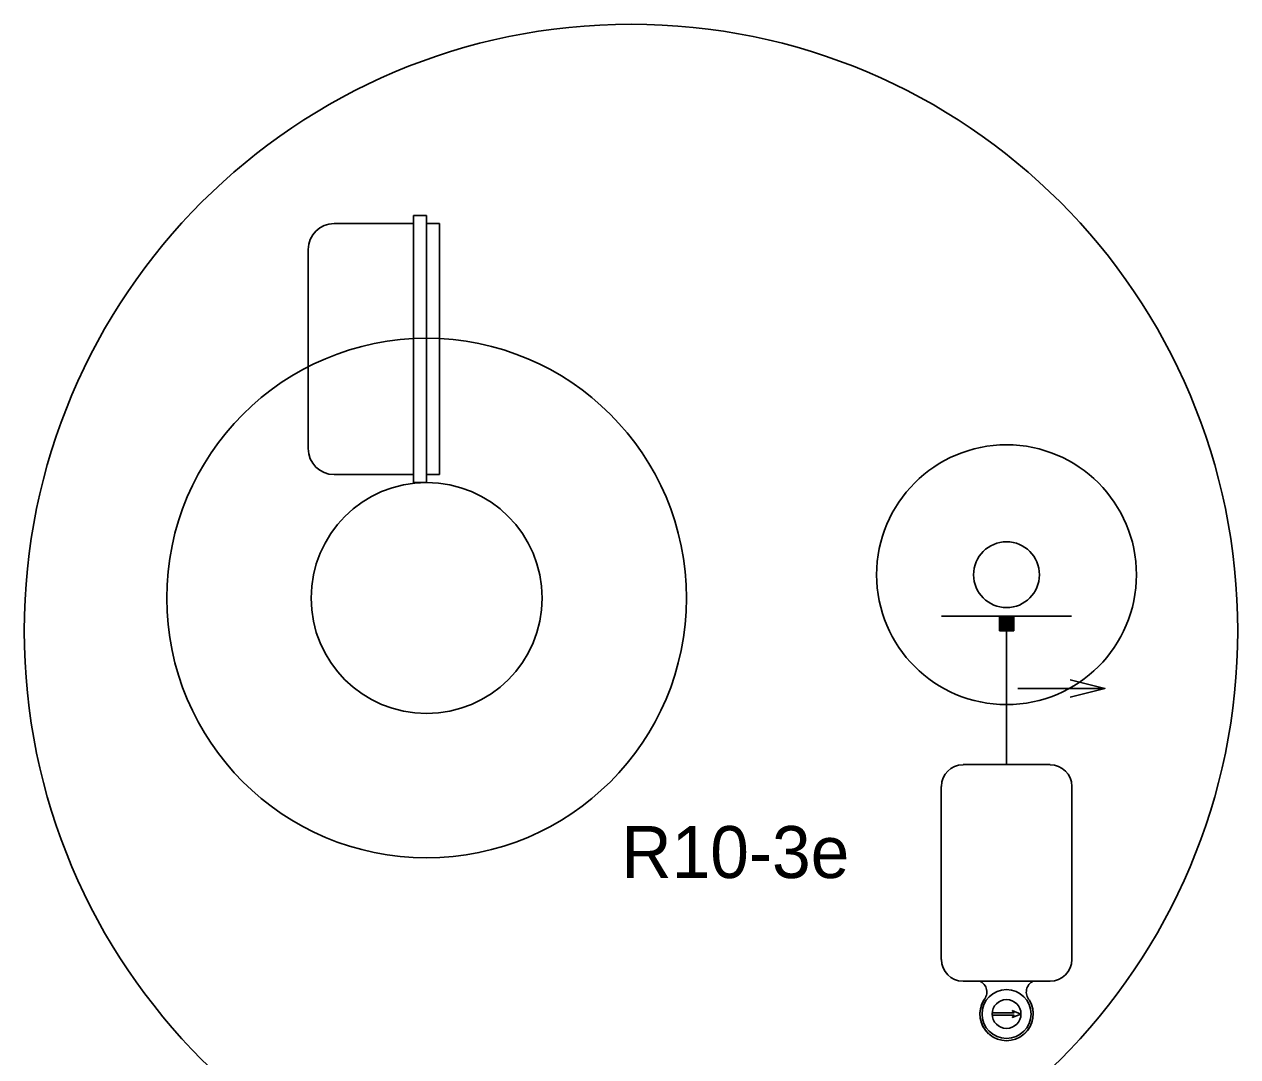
# Model space of a CAD drawing. Extents: x 418532 to 420296, y -565948 to -565286.
# Drawn here: x 419463.9 to 419569, y -565709.5 to -565620 of the extents above; entities that cross this region are included whole.
import ezdxf

# ---------------------------------------------------------------- set-up
doc = ezdxf.new("R2010")
doc.units = 0
doc.layers.add('T_Drafting', color=7, linetype='Continuous')

msp = doc.modelspace()

# ---------------------------------------------------------------- linework, layer by layer
at = {"layer": 'T_Drafting'}
for p, q in [((419497.65, -565659.72), (419497.65, -565636.59)), ((419498.78, -565636.59), (419497.65, -565636.59)), ((419498.78, -565659.72), (419498.78, -565636.59)), ((419497.65, -565637.28), (419490.78, -565637.28)), ((419499.9, -565637.28), (419498.78, -565637.28)), ((419499.9, -565659.03), (419499.9, -565637.28)), ((419488.53, -565656.78), (419488.53, -565639.53)), ((419497.65, -565659.03), (419490.78, -565659.03)), ((419498.78, -565659.72), (419497.65, -565659.72)), ((419499.9, -565659.03), (419498.78, -565659.03)), ((419554.63, -565671.3), (419543.38, -565671.3)), ((419548.38, -565672.55), (419548.38, -565671.3)), ((419548.38, -565672.54), (419549.62, -565671.3)), ((419548.38, -565672.52), (419549.6, -565671.3)), ((419548.38, -565672.5), (419549.58, -565671.3)), ((419548.38, -565672.47), (419549.56, -565671.3)), ((419548.38, -565672.45), (419549.54, -565671.3)), ((419548.38, -565672.43), (419549.51, -565671.3)), ((419548.38, -565672.41), (419549.49, -565671.3)), ((419548.38, -565672.39), (419549.47, -565671.3)), ((419548.38, -565672.37), (419549.45, -565671.3)), ((419548.38, -565672.35), (419549.43, -565671.3)), ((419548.38, -565672.33), (419549.41, -565671.3)), ((419548.38, -565672.3), (419549.39, -565671.3)), ((419548.38, -565672.28), (419549.37, -565671.3)), ((419548.38, -565672.26), (419549.34, -565671.3)), ((419548.38, -565672.24), (419549.32, -565671.3)), ((419548.38, -565672.22), (419549.3, -565671.3)), ((419548.38, -565672.2), (419549.28, -565671.3)), ((419548.38, -565672.18), (419549.26, -565671.3)), ((419548.38, -565672.16), (419549.24, -565671.3)), ((419548.38, -565672.14), (419549.22, -565671.3)), ((419548.38, -565672.11), (419549.2, -565671.3)), ((419548.38, -565672.09), (419549.17, -565671.3)), ((419548.38, -565672.07), (419549.15, -565671.3)), ((419548.38, -565672.05), (419549.13, -565671.3)), ((419548.38, -565672.03), (419549.11, -565671.3)), ((419548.38, -565672.01), (419549.09, -565671.3)), ((419548.38, -565671.99), (419549.07, -565671.3)), ((419548.38, -565671.97), (419549.05, -565671.3)), ((419548.38, -565671.94), (419549.03, -565671.3)), ((419548.38, -565671.92), (419549.01, -565671.3)), ((419548.38, -565671.9), (419548.98, -565671.3)), ((419548.38, -565671.88), (419548.96, -565671.3)), ((419548.38, -565671.86), (419548.94, -565671.3)), ((419548.38, -565671.84), (419548.92, -565671.3)), ((419548.38, -565671.82), (419548.9, -565671.3)), ((419548.38, -565671.8), (419548.88, -565671.3)), ((419548.38, -565671.77), (419548.86, -565671.3)), ((419548.38, -565671.75), (419548.84, -565671.3)), ((419548.38, -565671.73), (419548.81, -565671.3)), ((419548.38, -565671.71), (419548.79, -565671.3)), ((419548.38, -565671.69), (419548.77, -565671.3)), ((419548.38, -565671.67), (419548.75, -565671.3)), ((419548.38, -565671.65), (419548.73, -565671.3)), ((419548.38, -565671.63), (419548.71, -565671.3)), ((419548.38, -565671.6), (419548.69, -565671.3)), ((419548.38, -565671.58), (419548.67, -565671.3)), ((419548.38, -565671.56), (419548.64, -565671.3)), ((419548.38, -565671.54), (419548.62, -565671.3)), ((419548.38, -565671.52), (419548.6, -565671.3)), ((419548.38, -565671.5), (419548.58, -565671.3)), ((419548.38, -565671.48), (419548.56, -565671.3)), ((419548.38, -565671.46), (419548.54, -565671.3)), ((419548.38, -565671.44), (419548.52, -565671.3)), ((419548.38, -565671.41), (419548.5, -565671.3)), ((419548.38, -565671.39), (419548.47, -565671.3)), ((419548.38, -565671.37), (419548.45, -565671.3)), ((419548.38, -565671.35), (419548.43, -565671.3)), ((419548.38, -565671.33), (419548.41, -565671.3)), ((419548.38, -565671.31), (419548.39, -565671.3)), ((419548.39, -565672.55), (419549.63, -565671.31)), ((419548.41, -565672.55), (419549.63, -565671.33)), ((419548.43, -565672.55), (419549.63, -565671.35)), ((419548.46, -565672.55), (419549.63, -565671.37)), ((419548.48, -565672.55), (419549.63, -565671.39)), ((419548.5, -565672.55), (419549.63, -565671.42)), ((419548.52, -565672.55), (419549.63, -565671.44)), ((419548.54, -565672.55), (419549.63, -565671.46)), ((419548.56, -565672.55), (419549.63, -565671.48)), ((419548.58, -565672.55), (419549.63, -565671.5)), ((419548.6, -565672.55), (419549.63, -565671.52)), ((419548.62, -565672.55), (419549.63, -565671.54)), ((419549.63, -565672.55), (419549.63, -565671.3)), ((419548.38, -565672.55), (419549.63, -565672.55)), ((419548.65, -565672.55), (419549.63, -565671.56)), ((419548.67, -565672.55), (419549.63, -565671.59)), ((419548.69, -565672.55), (419549.63, -565671.61)), ((419548.71, -565672.55), (419549.63, -565671.63)), ((419548.73, -565672.55), (419549.63, -565671.65)), ((419548.75, -565672.55), (419549.63, -565671.67)), ((419548.77, -565672.55), (419549.63, -565671.69)), ((419548.79, -565672.55), (419549.63, -565671.71)), ((419548.82, -565672.55), (419549.63, -565671.73)), ((419548.84, -565672.55), (419549.63, -565671.75)), ((419548.86, -565672.55), (419549.63, -565671.78)), ((419548.88, -565672.55), (419549.63, -565671.8)), ((419548.9, -565672.55), (419549.63, -565671.82)), ((419548.92, -565672.55), (419549.63, -565671.84)), ((419548.94, -565672.55), (419549.63, -565671.86)), ((419548.96, -565672.55), (419549.63, -565671.88)), ((419548.99, -565672.55), (419549.63, -565671.9)), ((419549, -565672.55), (419549, -565684.15)), ((419549.01, -565672.55), (419549.63, -565671.92)), ((419549.03, -565672.55), (419549.63, -565671.95)), ((419549.05, -565672.55), (419549.63, -565671.97)), ((419549.07, -565672.55), (419549.63, -565671.99)), ((419549.09, -565672.55), (419549.63, -565672.01)), ((419549.11, -565672.55), (419549.63, -565672.03)), ((419549.13, -565672.55), (419549.63, -565672.05)), ((419549.16, -565672.55), (419549.63, -565672.07)), ((419549.18, -565672.55), (419549.63, -565672.09)), ((419549.2, -565672.55), (419549.63, -565672.12)), ((419549.22, -565672.55), (419549.63, -565672.14)), ((419549.24, -565672.55), (419549.63, -565672.16)), ((419549.26, -565672.55), (419549.63, -565672.18)), ((419549.28, -565672.55), (419549.63, -565672.2)), ((419549.3, -565672.55), (419549.63, -565672.22)), ((419549.32, -565672.55), (419549.63, -565672.24)), ((419549.35, -565672.55), (419549.63, -565672.26)), ((419549.37, -565672.55), (419549.63, -565672.29)), ((419549.39, -565672.55), (419549.63, -565672.31)), ((419549.41, -565672.55), (419549.63, -565672.33)), ((419549.43, -565672.55), (419549.63, -565672.35)), ((419549.45, -565672.55), (419549.63, -565672.37)), ((419549.47, -565672.55), (419549.63, -565672.39)), ((419549.49, -565672.55), (419549.63, -565672.41)), ((419549.52, -565672.55), (419549.63, -565672.43)), ((419549.54, -565672.55), (419549.63, -565672.45)), ((419549.56, -565672.55), (419549.63, -565672.48)), ((419549.58, -565672.55), (419549.63, -565672.5)), ((419549.6, -565672.55), (419549.63, -565672.52)), ((419549.62, -565672.55), (419549.63, -565672.54)), ((419549.97, -565677.55), (419557.52, -565677.55)), ((419545.23, -565684.15), (419552.78, -565684.15)), ((419543.35, -565701.03), (419543.35, -565686.03)), ((419554.65, -565686.03), (419554.65, -565701.03)), ((419552.78, -565702.9), (419545.23, -565702.9)), ((419547.76, -565705.64), (419547.76, -565705.86)), ((419549.65, -565705.64), (419547.76, -565705.64)), ((419549.65, -565705.86), (419547.76, -565705.86)), ((419549.5, -565705.45), (419550.25, -565705.75)), ((419549.65, -565705.64), (419549.5, -565705.45)), ((419549.5, -565706.05), (419550.25, -565705.75)), ((419549.5, -565706.05), (419549.65, -565705.86))]:
    msp.add_line(p, q, dxfattribs=at)
msp.add_lwpolyline([(419554.52, -565676.8), (419557.52, -565677.55), (419554.52, -565678.3)], dxfattribs=at)
for centre, radius in [((419516.48, -565672.56), 52.54), ((419498.78, -565669.72), 22.5), ((419549, -565667.7), 11.25), ((419498.78, -565669.72), 10), ((419549, -565667.7), 2.85), ((419549, -565705.75), 2.12), ((419549, -565705.75), 1.25)]:
    msp.add_circle(centre, radius, dxfattribs=at)
for centre, radius, start, end in [((419490.78, -565639.53), 2.25, 90, 180), ((419490.78, -565656.78), 2.25, 180, 270), ((419545.23, -565686.03), 1.87, 90, 180), ((419552.78, -565686.03), 1.87, 0, 90), ((419545.23, -565701.03), 1.87, 180, 270), ((419552.78, -565701.03), 1.87, 270, 0), ((419546.24, -565703.85), 1.05, 318.1972, 64.8044), ((419551.76, -565703.85), 1.05, 115.1956, 221.8028), ((419549, -565705.75), 2.31, 148.7402, 227.4934), ((419549, -565705.75), 2.31, 148.7402, 31.2598), ((419549, -565705.75), 2.31, 312.5066, 31.2598)]:
    msp.add_arc(centre, radius, start, end, dxfattribs=at)

# ---------------------------------------------------------------- texts
msp.add_text('R10-3e', height=4.5, dxfattribs=at).set_placement((419515.65, -565693.97))

doc.saveas('drawing.dxf')
